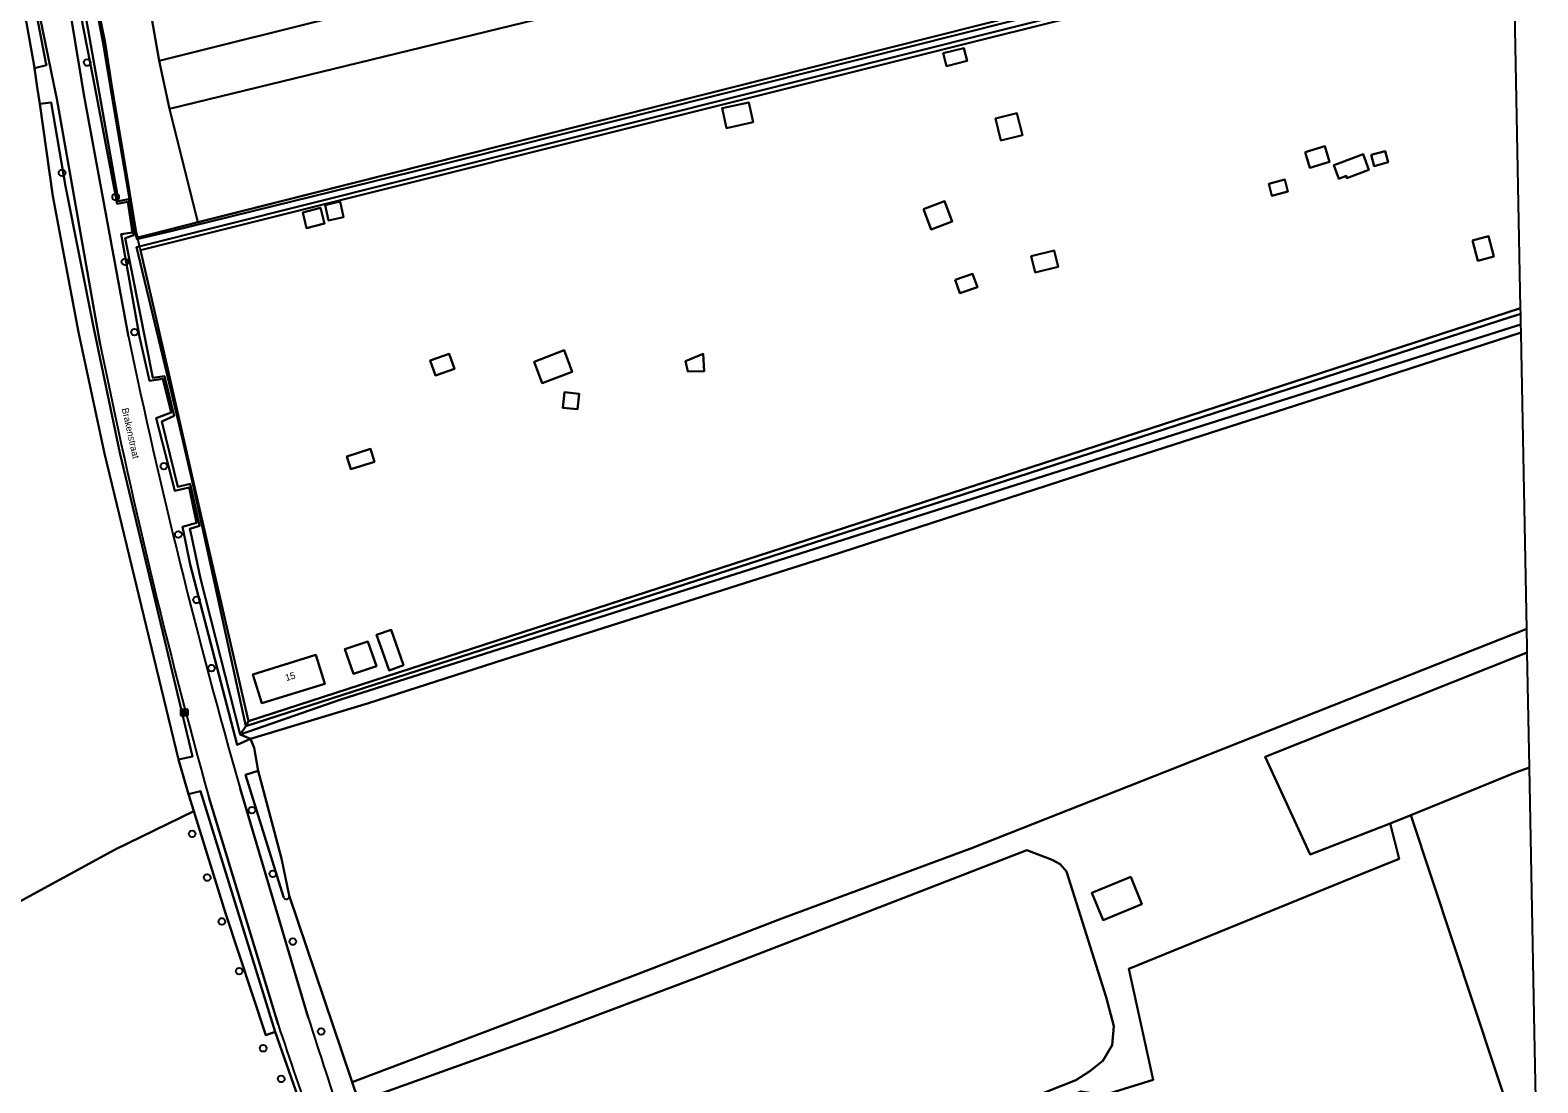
# Model space of a CAD drawing. Extents: x 163859 to 164644, y 379566 to 382155.
# Drawn here: x 164380.2 to 164601.7, y 381772.4 to 381926.9 of the extents above; entities that cross this region are included whole.
import ezdxf

# ---------------------------------------------------------------- set-up
doc = ezdxf.new("R2010")
doc.units = 0
for name, color, linetype in [('IMGEO_Boom', 7, 'Continuous'), ('IMGEO_Brandkraan', 7, 'Continuous'), ('IMGEO_Erf', 7, 'Continuous'), ('IMGEO_Grasland_agrarisch', 7, 'Continuous'), ('IMGEO_Grasland_overig', 7, 'Continuous'), ('IMGEO_Groenvoorziening', 7, 'Continuous'), ('IMGEO_Hek', 7, 'Continuous'), ('IMGEO_Oever', 7, 'Continuous'), ('IMGEO_Openbare_ruimte_label', 7, 'Continuous'), ('IMGEO_Pand', 7, 'Continuous'), ('IMGEO_Pand_nummerreeks', 7, 'Continuous'), ('IMGEO_Rijbaan_lokaal_halfverhard', 7, 'Continuous'), ('IMGEO_Waterloop', 7, 'Continuous')]:
    doc.layers.add(name, color=color, linetype=linetype)

msp = doc.modelspace()

# ---------------------------------------------------------------- linework, layer by layer
at = {"layer": 'IMGEO_Boom'}
for centre in [(164388.58, 381922.14), (164384.9, 381905.95), (164392.78, 381902.41), (164394.15, 381892.9), (164395.55, 381882.56), (164399.85, 381862.9), (164401.99, 381852.85), (164404.67, 381843.25), (164406.86, 381833.25), (164412.8, 381812.38), (164404.01, 381808.91), (164406.24, 381802.48), (164415.88, 381803.04), (164408.38, 381796.06), (164418.81, 381793.09), (164410.92, 381788.74), (164422.97, 381779.88), (164414.46, 381777.42), (164417.11, 381772.92)]:
    msp.add_circle(centre, 0.489, dxfattribs=at)
at = {"layer": 'IMGEO_Brandkraan'}
for p, q in [((164402.37, 381826.3), (164402.37, 381827.15)), ((164402.44, 381827.23), (164403.3, 381827.23)), ((164402.63, 381826.72), (164402.63, 381826.73)), ((164402.67, 381826.77), (164403.07, 381826.77)), ((164403.06, 381826.68), (164402.67, 381826.68)), ((164402.88, 381826.45), (164402.85, 381826.45)), ((164402.86, 381827.01), (164402.88, 381827.01)), ((164403.11, 381826.73), (164403.11, 381826.72)), ((164403.37, 381827.15), (164403.37, 381826.3)), ((164403.3, 381826.23), (164402.44, 381826.23))]:
    msp.add_line(p, q, dxfattribs=at)
for points in [[(164402.37, 381826.3), (164402.37, 381827.15)], [(164402.44, 381827.23), (164403.3, 381827.23)], [(164403.37, 381827.15), (164403.37, 381826.3)], [(164403.3, 381826.23), (164402.44, 381826.23)]]:
    msp.add_lwpolyline(points, dxfattribs=at)
for centre, radius, start, end in [((164402.44, 381827.15), 0.0765, 91.552, 178.448), ((164402.44, 381827.15), 0.0765, 91.552, 178.448), ((164402.67, 381826.73), 0.0403, 85.8775, 175.7526), ((164402.66, 381826.72), 0.0366, 178.938, 274.7102), ((164403.07, 381826.73), 0.043, 264.8664, 352.4533), ((164403.07, 381826.73), 0.0386, 1.7309, 96.639), ((164403.29, 381827.15), 0.0765, 1.552, 88.448), ((164403.29, 381827.15), 0.0765, 1.552, 88.448), ((164402.44, 381826.3), 0.0765, 181.552, 268.448), ((164402.44, 381826.3), 0.0765, 181.552, 268.448), ((164403.29, 381826.3), 0.0765, 271.552, 358.448), ((164403.29, 381826.3), 0.0765, 271.552, 358.448)]:
    msp.add_arc(centre, radius, start, end, dxfattribs=at)
for centre, major_axis, ratio, start_param, end_param in [((164402.86, 381826.73), (-0.387, 0.002), 0.722429, 4.712389, 7.853982), ((164402.88, 381826.73), (-0.39, 0.002), 0.717154, 1.570796, 4.712389)]:
    msp.add_ellipse(centre, major_axis=major_axis, ratio=ratio, start_param=start_param, end_param=end_param, dxfattribs=at)
at = {"layer": 'IMGEO_Erf'}
for points in [[(164474.95, 381933.46), (164475.9, 381929.85), (164477.68, 381929.91), (164487.97, 381932.24), (164503.9, 381936.71), (164502.01, 381945.59), (164495.78, 381944.03), (164490.52, 381942.71), (164489.77, 381945.71), (164495.04, 381947.03), (164501.37, 381948.61), (164498.89, 381960.27), (164474.03, 381954.47), (164476.09, 381940.68), (164450.64, 381934.85), (164427.22, 381929.39), (164399.15, 381922.42), (164400.69, 381915.35)], [(164600.1, 381839.01), (164585.23, 381833.12), (164548.83, 381818.75), (164518.64, 381806.88), (164490.64, 381796.47), (164469.45, 381788.32), (164427.55, 381772.44), (164433.53, 381754.8), (164434, 381752.73), (164434.33, 381751.74), (164440.83, 381734.26), (164457.1, 381740.6), (164468.83, 381745.17), (164534.65, 381771.11), (164538.09, 381770.59), (164545.19, 381772.8), (164541.61, 381789.07), (164575.75, 381802.97), (164581.35, 381805.25), (164580.01, 381810.41), (164568.26, 381805.89), (164561.67, 381820.23), (164600.16, 381835.55), (164600.15, 381836.16)], [(164443.54, 381737.47), (164442.94, 381737.25), (164436.97, 381753.01), (164430.96, 381770.51), (164456.78, 381779.76), (164478.35, 381787.87), (164505.55, 381798.32), (164526.66, 381806.51), (164530.39, 381805.09), (164531.54, 381804.48), (164532.49, 381803.4), (164538.3, 381784.94), (164539.44, 381780.67), (164539.19, 381777.89), (164537.82, 381775.6), (164535.89, 381774.09), (164533.83, 381772.76), (164490.02, 381755.43)], [(164541.92, 381802.59), (164543.55, 381798.61), (164537.85, 381796.26), (164536.21, 381800.24)]]:
    msp.add_lwpolyline(points, close=True, dxfattribs=at)
for points in [[(164421.55, 381764.61), (164416.2, 381779.85), (164414.83, 381779.35), (164408.91, 381797.24), (164404.25, 381812.22), (164392.73, 381806.6), (164338.75, 381777.23)], [(164601.59, 381755.85), (164583.08, 381811.66), (164580.01, 381810.41), (164581.35, 381805.25), (164575.75, 381802.97), (164541.61, 381789.07), (164545.19, 381772.8), (164538.09, 381770.59)]]:
    msp.add_lwpolyline(points, dxfattribs=at)
at = {"layer": 'IMGEO_Grasland_agrarisch'}
for points in [[(164393.11, 381957.21), (164399.15, 381922.42), (164427.22, 381929.39)], [(164474.95, 381933.46), (164400.69, 381915.35), (164404.87, 381898.71), (164500, 381922.69), (164597.99, 381947.39)], [(164338.75, 381777.23), (164392.73, 381806.6), (164404.25, 381812.22), (164403.47, 381814.73), (164402.01, 381819.81), (164391.12, 381864.73), (164387.32, 381882.58), (164383.56, 381902.54), (164381.64, 381916.11), (164381.27, 381918.53), (164380.84, 381921.34), (164380.79, 381921.68), (164378.81, 381932.98)]]:
    msp.add_lwpolyline(points, dxfattribs=at)
for points in [[(164599.26, 381882.52), (164575.73, 381874.87), (164537.18, 381862.49), (164497.51, 381849.65), (164449.86, 381834.52), (164429.92, 381828.12), (164412.59, 381822.86), (164413.11, 381821.55), (164413.73, 381818.17), (164417.16, 381805.27), (164418.25, 381799.85), (164427.35, 381773.02), (164427.55, 381772.44), (164469.45, 381788.32), (164490.64, 381796.47), (164518.64, 381806.88), (164548.83, 381818.75), (164585.23, 381833.12), (164600.1, 381839.01), (164599.31, 381879.67)], [(164600.49, 381818.66), (164600.16, 381835.55), (164561.67, 381820.23), (164568.26, 381805.89), (164580.01, 381810.41), (164583.08, 381811.66), (164593.07, 381815.71), (164598.45, 381817.9)], [(164601.72, 381755.45), (164601.25, 381779.75), (164600.49, 381818.66), (164598.45, 381817.9), (164593.07, 381815.71), (164583.08, 381811.66), (164601.59, 381755.85)], [(164443.54, 381737.47), (164490.02, 381755.43), (164533.83, 381772.76), (164535.89, 381774.09), (164537.82, 381775.6), (164539.19, 381777.89), (164539.44, 381780.67), (164538.3, 381784.94), (164532.49, 381803.4), (164531.54, 381804.48), (164530.39, 381805.09), (164526.66, 381806.51), (164505.55, 381798.32), (164478.35, 381787.87), (164456.78, 381779.76), (164430.96, 381770.51), (164436.97, 381753.01), (164442.94, 381737.25)]]:
    msp.add_lwpolyline(points, close=True, dxfattribs=at)
at = {"layer": 'IMGEO_Grasland_overig'}
msp.add_lwpolyline([(164385.1, 381955.18), (164391.22, 381925.04), (164392.24, 381918.62), (164392.84, 381914.85), (164394.3, 381906.15), (164395.74, 381897.51), (164395.98, 381896.47), (164398.12, 381897.01), (164404.87, 381898.71), (164400.69, 381915.35), (164399.15, 381922.42), (164393.11, 381957.21)], close=True, dxfattribs=at)
at = {"layer": 'IMGEO_Groenvoorziening'}
for points in [[(164377.32, 381999.91), (164375, 382024.99), (164374.98, 382025.23), (164374.69, 382027.13), (164374.12, 382027.07), (164373.56, 382027.01), (164371.07, 382052.25), (164369.31, 382067.96), (164367.5, 382080), (164366.21, 382089.98), (164363.36, 382106.67), (164361.94, 382106.41), (164362.19, 382105.09), (164364.66, 382091.74), (164366.23, 382081.36), (164368.33, 382065.24), (164375.07, 382000), (164376.33, 381987.84), (164377.03, 381983.08), (164379.47, 381969.66), (164387.74, 381919.59), (164388.1, 381917.44), (164394.68, 381881.88)], [(164390.52, 381880.76), (164384.14, 381916.84), (164383.71, 381918.93), (164381.31, 381930.61), (164377.52, 381953.78), (164372.7, 381981.96), (164370.62, 382000), (164365.91, 382044.84), (164361.43, 382082.09), (164360.43, 382089.08), (164359.08, 382087.82)], [(164380.3, 381933.65), (164382.52, 381922.1), (164382.6, 381921.75), (164380.84, 381921.34), (164381.27, 381918.53), (164381.64, 381916.11), (164383.28, 381916.29), (164385.41, 381903.99), (164389.55, 381883.1), (164393.37, 381864.87), (164404.05, 381820.29), (164402.01, 381819.81), (164403.47, 381814.73), (164405.26, 381815.2), (164416.2, 381779.85), (164421.55, 381764.61)], [(164417.42, 381799.68), (164411.85, 381817.58), (164413.73, 381818.17), (164413.11, 381821.55), (164412.59, 381822.86), (164410.64, 381821.98), (164403.71, 381848.45), (164402.59, 381853.99), (164404.68, 381854.55), (164403.57, 381859.74), (164401.45, 381859.25), (164398.75, 381869.96), (164400.94, 381870.79), (164399.72, 381875.7), (164397.74, 381875.4), (164396.26, 381881.9), (164393.58, 381896.98), (164395.23, 381897.19), (164394.58, 381901.69), (164393.01, 381901.42), (164389.46, 381919.87), (164386.85, 381933.44)], [(164411.08, 381815.56), (164421.07, 381781.95)], [(164416.64, 381780.93), (164406.46, 381814.29)], [(164455.9, 381683.82), (164455.77, 381683.63), (164466.53, 381676.14), (164470.41, 381677.43), (164460.51, 381684.89), (164456.24, 381696.23), (164452.84, 381705.1), (164451.1, 381709.42), (164447.31, 381716.53), (164449.31, 381717.49), (164446.86, 381722.17), (164445.22, 381721.44), (164440.48, 381732.58), (164442.12, 381733.05), (164440.83, 381734.26), (164434.33, 381751.74), (164434, 381752.73), (164433.53, 381754.8), (164427.55, 381772.44), (164427.35, 381773.02), (164418.25, 381799.85)]]:
    msp.add_lwpolyline(points, dxfattribs=at)
for points in [[(164598.04, 381945.02), (164500, 381920.51), (164396.41, 381894.6), (164400.28, 381877.79), (164404.82, 381857.96), (164412.31, 381825.45), (164500, 381853.89), (164599.19, 381886.07)], [(164514.35, 381923.51), (164517.4, 381924.27), (164517.87, 381922.41), (164514.82, 381921.64)], [(164482.52, 381912.54), (164481.88, 381915.45), (164485.81, 381916.31), (164486.45, 381913.4)], [(164522.03, 381913.93), (164525.2, 381914.72), (164526.01, 381911.48), (164522.84, 381910.69)], [(164567.52, 381909.01), (164570.43, 381909.89), (164571.13, 381907.6), (164568.22, 381906.71)], [(164571.73, 381907.07), (164572.81, 381907.47), (164576.07, 381908.68), (164576.91, 381906.41), (164573.65, 381905.2), (164573.54, 381905.5), (164572.46, 381905.1)], [(164577.23, 381908.59), (164579.27, 381909.15), (164579.72, 381907.51), (164577.67, 381906.95)], [(164562.18, 381904.34), (164564.53, 381904.97), (164565, 381903.22), (164562.65, 381902.59)], [(164426.27, 381899.47), (164424.07, 381898.96), (164423.54, 381901.23), (164425.74, 381901.74)], [(164511.47, 381900.63), (164514.55, 381901.78), (164515.66, 381898.8), (164512.58, 381897.65)], [(164420.84, 381897.86), (164420.26, 381900.14), (164422.87, 381900.8), (164423.45, 381898.52)], [(164592.1, 381896.03), (164594.46, 381896.67), (164595.27, 381893.7), (164592.91, 381893.06)], [(164527.29, 381893.71), (164530.67, 381894.55), (164531.26, 381892.18), (164527.88, 381891.34)], [(164516.11, 381890.24), (164518.68, 381891.15), (164519.38, 381889.18), (164516.8, 381888.28)], [(164459.85, 381876.73), (164455.45, 381875.07), (164454.25, 381878.23), (164458.66, 381879.9)], [(164442.58, 381877.19), (164439.77, 381876.2), (164438.99, 381878.42), (164441.8, 381879.41)], [(164479.26, 381876.82), (164476.86, 381876.77), (164476.5, 381878.3), (164479.09, 381879.38)], [(164460.86, 381873.53), (164460.64, 381871.24), (164458.48, 381871.46), (164458.7, 381873.74)], [(164430.82, 381863.55), (164427.33, 381862.43), (164426.73, 381864.31), (164430.22, 381865.43)], [(164435.08, 381833.66), (164432.94, 381832.91), (164431.96, 381835.7), (164431.11, 381838.11), (164433.24, 381838.86)], [(164431.08, 381833.54), (164427.72, 381832.39), (164426.47, 381836.02), (164429.83, 381837.17)], [(164422.18, 381835.18), (164423.49, 381830.94), (164414.26, 381828.09), (164412.95, 381832.33)]]:
    msp.add_lwpolyline(points, close=True, dxfattribs=at)
for centre, radius, start, end in [((165292.34, 382068.69), 916.9, 191.75614, 196.0263), ((165324.24, 382069.52), 952.61, 191.4287, 195.54119), ((164417.84, 381799.75), 0.425, 188.4757, 14.7527), ((165706.5, 382210.95), 1359.65, 198.43767, 199.81713), ((165106.27, 381998.23), 718.53, 197.51825, 200.2104)]:
    msp.add_arc(centre, radius, start, end, dxfattribs=at)
at = {"layer": 'IMGEO_Hek'}
for points in [[(164385.1, 381955.18), (164391.22, 381925.04), (164392.24, 381918.62)], [(164395.98, 381896.47), (164398.12, 381897.01), (164500, 381922.69), (164597.99, 381947.39)], [(164598.04, 381945.02), (164500, 381920.51), (164396.41, 381894.6)], [(164392.24, 381918.62), (164392.84, 381914.85)], [(164395.74, 381897.51), (164394.3, 381906.15), (164392.84, 381914.85)], [(164395.98, 381896.47), (164395.74, 381897.51)], [(164396.41, 381894.6), (164395.98, 381896.47)], [(164412.31, 381825.45), (164404.82, 381857.96), (164400.28, 381877.79), (164396.41, 381894.6)], [(164412.31, 381825.45), (164500, 381853.89), (164599.19, 381886.07)], [(164593.07, 381815.71), (164598.45, 381817.9)]]:
    msp.add_lwpolyline(points, dxfattribs=at)
at = {"layer": 'IMGEO_Oever'}
for points in [[(164597.99, 381947.39), (164500, 381922.69), (164404.87, 381898.71), (164398.12, 381897.01), (164395.98, 381896.47), (164395.74, 381897.51), (164394.3, 381906.15), (164392.84, 381914.85), (164392.24, 381918.62), (164391.22, 381925.04), (164385.1, 381955.18)], [(164389.26, 381933.7), (164390.96, 381924.95), (164392.83, 381913.56), (164394.08, 381906.41), (164395.58, 381897.61), (164395.88, 381896.29), (164395.9, 381896.21), (164400.92, 381897.42), (164436.61, 381906.17), (164597.14, 381946.58)], [(164597.23, 381945.58), (164395.83, 381895.07), (164402.11, 381868.95), (164404.15, 381860.08), (164411.92, 381824.73), (164412.31, 381825.45), (164404.82, 381857.96), (164400.28, 381877.79), (164396.41, 381894.6), (164500, 381920.51), (164598.04, 381945.02)], [(164386.85, 381933.44), (164389.46, 381919.87), (164393.01, 381901.42), (164394.58, 381901.69), (164395.23, 381897.19), (164393.58, 381896.98), (164396.26, 381881.9), (164397.74, 381875.4), (164399.72, 381875.7), (164400.94, 381870.79), (164398.75, 381869.96), (164401.45, 381859.25), (164403.57, 381859.74), (164404.68, 381854.55), (164402.59, 381853.99), (164403.71, 381848.45), (164410.64, 381821.98), (164412.59, 381822.86), (164411.07, 381823.48), (164405.25, 381846.41), (164403.98, 381852.44), (164403.68, 381853.71), (164405.1, 381854.12), (164403.74, 381860.3), (164401.92, 381859.87), (164399.54, 381869.47), (164401.36, 381870.27), (164399.96, 381876.09), (164398.26, 381875.88), (164394.19, 381896.39), (164395.46, 381896.81), (164394.68, 381902.1), (164393.21, 381901.8), (164387.75, 381932.48)]]:
    msp.add_lwpolyline(points, dxfattribs=at)
for points in [[(164599.19, 381886.07), (164500, 381853.89), (164412.31, 381825.45), (164411.92, 381824.73), (164525.3, 381861.33), (164597.65, 381884.75), (164599.21, 381885.24)], [(164599.26, 381882.52), (164599.26, 381882.67), (164599.24, 381883.67), (164597.82, 381883.23), (164425.84, 381828.62), (164411.07, 381823.48), (164412.59, 381822.86), (164429.92, 381828.12), (164449.86, 381834.52), (164497.51, 381849.65), (164537.18, 381862.49), (164575.73, 381874.87)]]:
    msp.add_lwpolyline(points, close=True, dxfattribs=at)
at = {"layer": 'IMGEO_Pand'}
for points in [[(164514.35, 381923.51), (164514.82, 381921.64), (164517.87, 381922.41), (164517.4, 381924.27)], [(164481.88, 381915.45), (164482.52, 381912.54), (164486.45, 381913.4), (164485.81, 381916.31)], [(164522.03, 381913.93), (164522.84, 381910.69), (164526.01, 381911.48), (164525.2, 381914.72)], [(164567.52, 381909.01), (164568.22, 381906.71), (164571.13, 381907.6), (164570.43, 381909.89)], [(164572.81, 381907.47), (164571.73, 381907.07), (164572.46, 381905.1), (164573.54, 381905.5), (164573.65, 381905.2), (164576.91, 381906.41), (164576.07, 381908.68)], [(164577.23, 381908.59), (164577.67, 381906.95), (164579.72, 381907.51), (164579.27, 381909.15)], [(164562.18, 381904.34), (164562.65, 381902.59), (164565, 381903.22), (164564.53, 381904.97)], [(164423.54, 381901.23), (164424.07, 381898.96), (164426.27, 381899.47), (164425.74, 381901.74)], [(164511.47, 381900.63), (164512.58, 381897.65), (164515.66, 381898.8), (164514.55, 381901.78)], [(164420.26, 381900.14), (164420.84, 381897.86), (164423.45, 381898.52), (164422.87, 381900.8)], [(164592.1, 381896.03), (164592.91, 381893.06), (164595.27, 381893.7), (164594.46, 381896.67)], [(164527.29, 381893.71), (164527.88, 381891.34), (164531.26, 381892.18), (164530.67, 381894.55)], [(164516.11, 381890.24), (164516.8, 381888.28), (164519.38, 381889.18), (164518.68, 381891.15)], [(164454.25, 381878.23), (164455.45, 381875.07), (164459.85, 381876.73), (164458.66, 381879.9)], [(164438.99, 381878.42), (164439.77, 381876.2), (164442.58, 381877.19), (164441.8, 381879.41)], [(164479.09, 381879.38), (164476.5, 381878.3), (164476.86, 381876.77), (164479.26, 381876.82)], [(164458.48, 381871.46), (164460.64, 381871.24), (164460.86, 381873.53), (164458.7, 381873.74)], [(164426.73, 381864.31), (164427.33, 381862.43), (164430.82, 381863.55), (164430.22, 381865.43)], [(164431.11, 381838.11), (164431.96, 381835.7), (164432.94, 381832.91), (164435.08, 381833.66), (164433.24, 381838.86)], [(164426.47, 381836.02), (164427.72, 381832.39), (164431.08, 381833.54), (164429.83, 381837.17)], [(164412.95, 381832.33), (164414.26, 381828.09), (164423.49, 381830.94), (164422.18, 381835.18)], [(164541.92, 381802.59), (164536.21, 381800.24), (164537.85, 381796.26), (164543.55, 381798.61)]]:
    msp.add_lwpolyline(points, close=True, dxfattribs=at)
at = {"layer": 'IMGEO_Rijbaan_lokaal_halfverhard'}
for points in [[(164394.68, 381881.88), (164388.1, 381917.44), (164387.74, 381919.59), (164379.47, 381969.66), (164377.03, 381983.08), (164376.33, 381987.84), (164375.07, 382000), (164368.33, 382065.24), (164366.23, 382081.36), (164364.66, 382091.74), (164362.19, 382105.09), (164359.32, 382104.56), (164361.73, 382090.28), (164360.43, 382089.08)], [(164360.43, 382089.08), (164361.43, 382082.09), (164365.91, 382044.84), (164370.62, 382000), (164372.7, 381981.96), (164377.52, 381953.78), (164381.31, 381930.61), (164383.71, 381918.93), (164384.14, 381916.84), (164390.52, 381880.76)], [(164421.07, 381781.95), (164411.08, 381815.56)], [(164406.46, 381814.29), (164416.64, 381780.93)]]:
    msp.add_lwpolyline(points, dxfattribs=at)
for centre, radius, start, end in [((165292.34, 382068.69), 916.9, 191.75614, 196.0263), ((165324.24, 382069.52), 952.61, 191.4287, 195.54119), ((165706.5, 382210.95), 1359.65, 198.43767, 199.81713), ((165106.27, 381998.23), 718.53, 197.51825, 200.2104)]:
    msp.add_arc(centre, radius, start, end, dxfattribs=at)
at = {"layer": 'IMGEO_Waterloop'}
for points in [[(164597.14, 381946.58), (164436.61, 381906.17), (164400.92, 381897.42), (164395.9, 381896.21), (164395.88, 381896.29), (164395.58, 381897.61), (164394.08, 381906.41), (164392.83, 381913.56), (164390.96, 381924.95), (164389.26, 381933.7)], [(164387.75, 381932.48), (164393.21, 381901.8), (164394.68, 381902.1), (164395.46, 381896.81), (164394.19, 381896.39), (164398.26, 381875.88), (164399.96, 381876.09), (164401.36, 381870.27), (164399.54, 381869.47), (164401.92, 381859.87), (164403.74, 381860.3), (164405.1, 381854.12), (164403.68, 381853.71), (164403.98, 381852.44), (164405.25, 381846.41), (164411.07, 381823.48), (164411.92, 381824.73), (164404.15, 381860.08), (164402.11, 381868.95), (164395.83, 381895.07), (164597.23, 381945.58)], [(164378.81, 381932.98), (164380.79, 381921.68), (164380.84, 381921.34), (164382.6, 381921.75), (164382.52, 381922.1), (164380.3, 381933.65)], [(164418.25, 381799.85), (164417.16, 381805.27), (164413.73, 381818.17), (164411.85, 381817.58), (164417.42, 381799.68)]]:
    msp.add_lwpolyline(points, dxfattribs=at)
for points in [[(164389.55, 381883.1), (164385.41, 381903.99), (164383.28, 381916.29), (164381.64, 381916.11), (164383.56, 381902.54), (164387.32, 381882.58), (164391.12, 381864.73), (164402.01, 381819.81), (164404.05, 381820.29), (164393.37, 381864.87)], [(164599.21, 381885.24), (164597.65, 381884.75), (164525.3, 381861.33), (164411.92, 381824.73), (164411.07, 381823.48), (164425.84, 381828.62), (164597.82, 381883.23), (164599.24, 381883.67)], [(164416.2, 381779.85), (164405.26, 381815.2), (164403.47, 381814.73), (164404.25, 381812.22), (164408.91, 381797.24), (164414.83, 381779.35)]]:
    msp.add_lwpolyline(points, close=True, dxfattribs=at)
msp.add_arc((164417.84, 381799.75), 0.425, 188.4757, 14.7527, dxfattribs=at)

# ---------------------------------------------------------------- texts
at = {"layer": 'IMGEO_Openbare_ruimte_label'}
msp.add_text('Brakenstraat', height=1, rotation=282.591, dxfattribs=at).set_placement((164393.66, 381871.32))
at = {"layer": 'IMGEO_Pand_nummerreeks'}
msp.add_text('15', height=1, rotation=17.1314, dxfattribs=at).set_placement((164417.86, 381831.32))

doc.saveas('drawing.dxf')
